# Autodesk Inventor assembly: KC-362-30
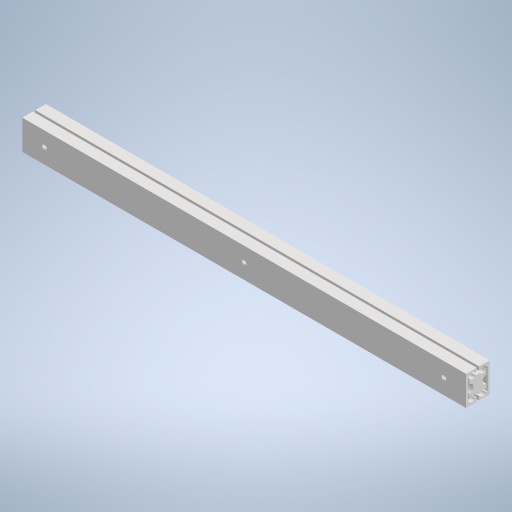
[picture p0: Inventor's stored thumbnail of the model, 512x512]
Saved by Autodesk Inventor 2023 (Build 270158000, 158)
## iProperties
Created: 2022-09
Part Number: KC-362-30
Document SubType Name: Assembly
Designer: deli
Author: deli
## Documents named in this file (3)
- C:\Users\deli\OneDrive - Eastside Preparatory School\FTC\8103-power-play\CAD\FTC-parts\KC-362-30.iam
- C:\Users\deli\OneDrive - Eastside Preparatory School\FTC\Freight Frenzy\Outside.ipt
- C:\Users\deli\OneDrive - Eastside Preparatory School\FTC\Freight Frenzy\KC-362-30 Middle.ipt
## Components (3 placed, 2 different names)
1. Outside:1
2. KC-362-30 Middle:1
3. Outside:2
## Named parameters: d12_d3 = 0, d13_d4 = 0, d14_d5 = 0, d15_d6 = 0
